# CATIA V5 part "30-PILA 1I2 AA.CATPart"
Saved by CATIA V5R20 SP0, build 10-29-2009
Part number: 30-PILA 1I2 AA
Revision: ANY
Definition: UNKNOWN
Nomenclature: 30-PILA 1I2 AA
Source: Unknown
Bounding box of the stored display mesh (mm): x -7 to 7, y -6.824 to 6.824, z 0 to 25.5
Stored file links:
  C:\Users\Utente\Desktop\IO LAVORO\3D X SITO CF\CUMSA\3D files CC\CCHS5328\30-PILA 1I2 AA.CATPart
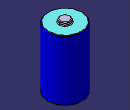
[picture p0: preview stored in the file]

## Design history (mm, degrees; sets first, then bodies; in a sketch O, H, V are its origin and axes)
Body1 "Redondeo1" (main body)
  Solid1: solid without history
